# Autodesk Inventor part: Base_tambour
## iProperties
Shininess: 64.0
Length Units: 11269
Angle Units: 11279
Time Units: 11290
Mass Units: 11283
Length Display Precision: 3
Angle Display Precision: 2
Compacted: True
Part Number: Base_tambour
Document SubType Name: Modeling
Created: 2008-02
Material: Acier inoxydable, austénitique
Designer: Pascal
Density: 0.0
Volumn: 0.0
Area: 0.0
PropertySet Name: Model Information
Control State: 0
Master: False
Checked Out: False
DESIGNATION: pièce
Author: Pascal
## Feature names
1. Extrusion1
